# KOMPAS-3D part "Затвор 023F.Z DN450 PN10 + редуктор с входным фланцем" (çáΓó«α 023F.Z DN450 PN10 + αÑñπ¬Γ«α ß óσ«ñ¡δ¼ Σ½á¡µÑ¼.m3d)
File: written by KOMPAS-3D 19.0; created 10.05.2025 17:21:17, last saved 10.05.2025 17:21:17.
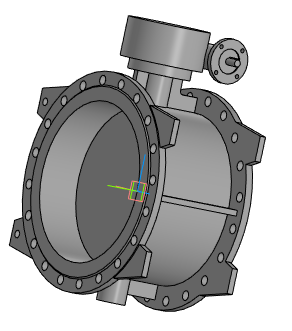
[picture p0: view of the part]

Document properties: Полное имя файла: Затвор 023F.Z DN450 PN10 + редуктор с входным фланцем.a3d

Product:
- Part/product: Затвор 023F.Z DN450 PN10 + редуктор с входным фланцем
    Масса: 222.795

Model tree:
1. Операция без истории:1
